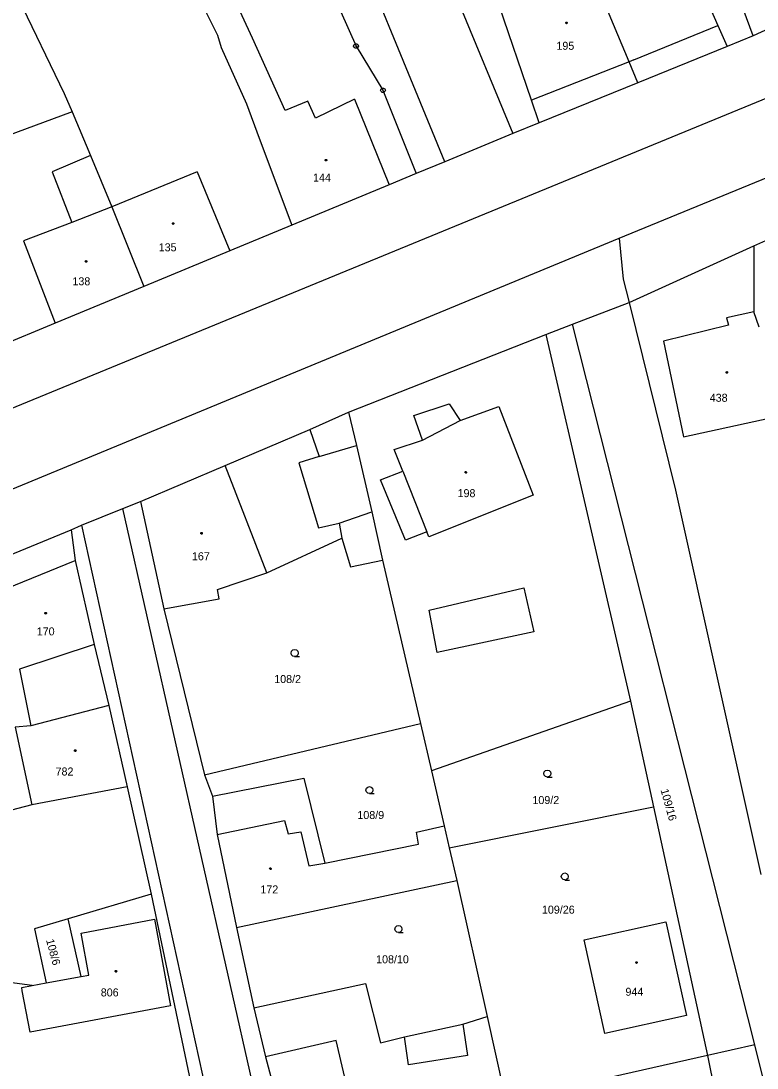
# Model space of a CAD drawing. Extents: x -757994 to -755874, y -1047691 to -1046119.
# Drawn here: x -756609.7 to -756531.6, y -1046918.4 to -1046807.2 of the extents above; entities that cross this region are included whole.
import ezdxf

# ---------------------------------------------------------------- set-up
doc = ezdxf.new("R2010")
doc.units = 0
doc.layers.add('katastrální mapa', color=7, linetype='Continuous')

msp = doc.modelspace()

# ---------------------------------------------------------------- linework, layer by layer
at = {"layer": 'katastrální mapa'}
for p, q in [((-756627.02, -1046769.47), (-756605.13, -1046814.89)), ((-756612.98, -1046849.23), (-756440.95, -1046778.5)), ((-756540.07, -1046797.73), (-756535.71, -1046807.66)), ((-756545.15, -1046811.51), (-756549.35, -1046801.44)), ((-756546.19, -1046830.24), (-756476.55, -1046801.65)), ((-756564.54, -1046802.11), (-756557.5, -1046819.13)), ((-756585.13, -1046808.98), (-756587.56, -1046803.75)), ((-756590.66, -1046805.08), (-756588.87, -1046808.69)), ((-756523.9, -1046805.07), (-756531.97, -1046808.74)), ((-756555.52, -1046815.57), (-756558.94, -1046805.54)), ((-756531.97, -1046808.74), (-756533.02, -1046805.87)), ((-756544.64, -1046811.31), (-756535.71, -1046807.66)), ((-756535.71, -1046807.66), (-756534.74, -1046809.87)), ((-756588.87, -1046808.69), (-756588.47, -1046810)), ((-756581.66, -1046816.68), (-756585.13, -1046808.98)), ((-756531.97, -1046808.74), (-756534.74, -1046809.87)), ((-756588.47, -1046810), (-756585.76, -1046815.97)), ((-756574.2, -1046809.83), (-756574.08, -1046809.83)), ((-756534.74, -1046809.87), (-756544.22, -1046813.73)), ((-756545.15, -1046811.51), (-756555.52, -1046815.57)), ((-756544.64, -1046811.31), (-756545.15, -1046811.51)), ((-756544.22, -1046813.73), (-756545.15, -1046811.51)), ((-756544.22, -1046813.73), (-756554.7, -1046817.99)), ((-756605.13, -1046814.89), (-756604.28, -1046816.83)), ((-756571.34, -1046814.53), (-756571.22, -1046814.53)), ((-756585.76, -1046815.97), (-756584.42, -1046819.61)), ((-756579.26, -1046815.68), (-756581.66, -1046816.68)), ((-756578.43, -1046817.51), (-756579.26, -1046815.68)), ((-756574.3, -1046815.48), (-756578.43, -1046817.51)), ((-756574.3, -1046815.48), (-756570.62, -1046824.57)), ((-756554.7, -1046817.99), (-756555.52, -1046815.57)), ((-756604.28, -1046816.83), (-756615.03, -1046820.81)), ((-756604.28, -1046816.83), (-756602.34, -1046821.46)), ((-756554.7, -1046817.99), (-756557.5, -1046819.13)), ((-756584.42, -1046819.61), (-756580.97, -1046828.86)), ((-756557.5, -1046819.13), (-756564.73, -1046822.13)), ((-756602.34, -1046821.46), (-756606.43, -1046823.18)), ((-756602.34, -1046821.46), (-756600.06, -1046826.91)), ((-756564.73, -1046822.13), (-756567.75, -1046823.38)), ((-756606.43, -1046823.18), (-756604.33, -1046828.56)), ((-756591.01, -1046823.2), (-756600.06, -1046826.91)), ((-756591.01, -1046823.2), (-756587.53, -1046831.58)), ((-756568.87, -1046823.84), (-756570.62, -1046824.57)), ((-756567.75, -1046823.38), (-756568.87, -1046823.84)), ((-756570.62, -1046824.57), (-756580.97, -1046828.86)), ((-756600.06, -1046826.91), (-756604.33, -1046828.56)), ((-756600.06, -1046826.91), (-756596.68, -1046835.37)), ((-756604.33, -1046828.56), (-756609.46, -1046830.53)), ((-756580.97, -1046828.86), (-756587.53, -1046831.58)), ((-756531.88, -1046831.06), (-756527.35, -1046829.01)), ((-756698.86, -1046893.31), (-756546.19, -1046830.24)), ((-756609.46, -1046830.53), (-756606.1, -1046839.27)), ((-756546.19, -1046830.24), (-756545.76, -1046834.59)), ((-756587.53, -1046831.58), (-756596.68, -1046835.37)), ((-756545.15, -1046837.07), (-756531.88, -1046831.06)), ((-756531.88, -1046831.06), (-756531.88, -1046838.07)), ((-756545.76, -1046834.59), (-756545.15, -1046837.07)), ((-756596.68, -1046835.37), (-756606.1, -1046839.27)), ((-756551.17, -1046839.38), (-756545.15, -1046837.07)), ((-756545.15, -1046837.07), (-756540.22, -1046857.01)), ((-756531.88, -1046838.07), (-756534.8, -1046838.69)), ((-756531.33, -1046839.67), (-756531.88, -1046838.07)), ((-756606.1, -1046839.27), (-756613.31, -1046842.26)), ((-756553.98, -1046840.46), (-756551.17, -1046839.38)), ((-756531.78, -1046915.9), (-756551.17, -1046839.38)), ((-756534.6, -1046839.46), (-756541.49, -1046841.19)), ((-756534.8, -1046838.69), (-756534.6, -1046839.46)), ((-756574.93, -1046848.73), (-756553.98, -1046840.46)), ((-756553.98, -1046840.46), (-756545, -1046879.4)), ((-756541.49, -1046841.19), (-756539.35, -1046851.35)), ((-756568.02, -1046849.08), (-756564.25, -1046847.83)), ((-756564.25, -1046847.83), (-756563.1, -1046849.6)), ((-756563.1, -1046849.6), (-756558.98, -1046848.12)), ((-756558.98, -1046848.12), (-756555.32, -1046857.52)), ((-756579.05, -1046850.56), (-756574.93, -1046848.73)), ((-756574.93, -1046848.73), (-756574.11, -1046852.27)), ((-756567.09, -1046851.7), (-756568.02, -1046849.08)), ((-756567.09, -1046851.7), (-756563.1, -1046849.6)), ((-756539.35, -1046851.35), (-756529.15, -1046849.09)), ((-756588.05, -1046854.37), (-756579.05, -1046850.56)), ((-756579.05, -1046850.56), (-756578.06, -1046853.43)), ((-756570.09, -1046852.68), (-756567.09, -1046851.7)), ((-756578.06, -1046853.43), (-756574.11, -1046852.27)), ((-756574.11, -1046852.27), (-756572.46, -1046859.3)), ((-756569.19, -1046854.97), (-756570.09, -1046852.68)), ((-756578.06, -1046853.43), (-756580.22, -1046854.09)), ((-756580.22, -1046854.09), (-756578.13, -1046860.99)), ((-756597.02, -1046858.19), (-756588.05, -1046854.37)), ((-756583.6, -1046865.78), (-756588.05, -1046854.37)), ((-756571.56, -1046855.91), (-756569.19, -1046854.97)), ((-756569.19, -1046854.97), (-756566.62, -1046861.43)), ((-756568.88, -1046862.29), (-756571.56, -1046855.91)), ((-756555.32, -1046857.52), (-756566.42, -1046861.96)), ((-756540.22, -1046857.01), (-756531.14, -1046897.8)), ((-756598.91, -1046858.96), (-756597.02, -1046858.19)), ((-756597.02, -1046858.19), (-756594.54, -1046869.59)), ((-756603.28, -1046860.72), (-756598.91, -1046858.96)), ((-756558.92, -1047036.01), (-756598.91, -1046858.96)), ((-756575.93, -1046860.49), (-756572.46, -1046859.3)), ((-756572.46, -1046859.3), (-756571.34, -1046864.42)), ((-756604.39, -1046861.2), (-756603.28, -1046860.72)), ((-756603.28, -1046860.72), (-756564.51, -1047036.98)), ((-756578.13, -1046860.99), (-756575.93, -1046860.49)), ((-756575.93, -1046860.49), (-756575.64, -1046862.11)), ((-756614.27, -1046865.28), (-756604.39, -1046861.2)), ((-756604.39, -1046861.2), (-756603.96, -1046864.46)), ((-756566.62, -1046861.43), (-756568.88, -1046862.29)), ((-756566.42, -1046861.96), (-756566.62, -1046861.43)), ((-756583.6, -1046865.78), (-756575.64, -1046862.11)), ((-756575.64, -1046862.11), (-756574.74, -1046865.13)), ((-756613.08, -1046868.17), (-756603.96, -1046864.46)), ((-756603.96, -1046864.46), (-756601.95, -1046873.39)), ((-756574.74, -1046865.13), (-756571.34, -1046864.42)), ((-756571.34, -1046864.42), (-756567.28, -1046881.77)), ((-756588.84, -1046867.54), (-756583.6, -1046865.78)), ((-756588.66, -1046868.55), (-756588.84, -1046867.54)), ((-756566.38, -1046869.73), (-756556.33, -1046867.36)), ((-756556.33, -1046867.36), (-756555.26, -1046872.03)), ((-756594.54, -1046869.59), (-756588.66, -1046868.55)), ((-756594.54, -1046869.59), (-756590.22, -1046887.21)), ((-756565.53, -1046874.23), (-756566.38, -1046869.73)), ((-756555.26, -1046872.03), (-756565.53, -1046874.23)), ((-756601.95, -1046873.39), (-756609.89, -1046875.99)), ((-756601.95, -1046873.39), (-756600.38, -1046879.88)), ((-756609.89, -1046875.99), (-756608.69, -1046882.01)), ((-756545, -1046879.4), (-756566.12, -1046886.81)), ((-756545, -1046879.4), (-756542.56, -1046890.64)), ((-756600.38, -1046879.88), (-756608.69, -1046882.01)), ((-756600.38, -1046879.88), (-756598.43, -1046888.49)), ((-756608.69, -1046882.01), (-756610.34, -1046882.18)), ((-756590.22, -1046887.21), (-756567.28, -1046881.77)), ((-756567.28, -1046881.77), (-756566.12, -1046886.81)), ((-756610.34, -1046882.18), (-756608.57, -1046890.43)), ((-756590.22, -1046887.21), (-756589.4, -1046889.5)), ((-756589.4, -1046889.5), (-756579.7, -1046887.58)), ((-756579.7, -1046887.58), (-756577.46, -1046896.61)), ((-756566.12, -1046886.81), (-756564.79, -1046892.63)), ((-756598.43, -1046888.49), (-756608.57, -1046890.43)), ((-756598.43, -1046888.49), (-756595.9, -1046899.9)), ((-756589.4, -1046889.5), (-756588.88, -1046893.57)), ((-756608.57, -1046890.43), (-756615.16, -1046892.14)), ((-756564.24, -1046894.99), (-756542.56, -1046890.64)), ((-756542.56, -1046890.64), (-756536.82, -1046917.03)), ((-756588.88, -1046893.57), (-756581.75, -1046892.06)), ((-756581.75, -1046892.06), (-756581.35, -1046893.48)), ((-756567.72, -1046893.32), (-756564.79, -1046892.63)), ((-756564.79, -1046892.63), (-756564.24, -1046894.99)), ((-756588.88, -1046893.57), (-756586.85, -1046903.44)), ((-756581.35, -1046893.48), (-756580.01, -1046893.28)), ((-756580.01, -1046893.28), (-756579.15, -1046896.9)), ((-756567.52, -1046894.58), (-756567.72, -1046893.32)), ((-756577.46, -1046896.61), (-756567.52, -1046894.58)), ((-756564.24, -1046894.99), (-756563.43, -1046898.44)), ((-756579.15, -1046896.9), (-756577.46, -1046896.61)), ((-756586.85, -1046903.44), (-756563.43, -1046898.44)), ((-756563.43, -1046898.44), (-756560.2, -1046912.9)), ((-756595.9, -1046899.9), (-756604.72, -1046902.52)), ((-756595.9, -1046899.9), (-756591.53, -1046920.69)), ((-756604.72, -1046902.52), (-756608.3, -1046903.59)), ((-756603.34, -1046908.65), (-756604.72, -1046902.52)), ((-756603.34, -1046904.04), (-756595.55, -1046902.54)), ((-756595.55, -1046902.54), (-756593.85, -1046911.75)), ((-756608.3, -1046903.59), (-756607.04, -1046909.33)), ((-756602.51, -1046908.5), (-756603.34, -1046904.04)), ((-756586.85, -1046903.44), (-756584.98, -1046911.96)), ((-756607.04, -1046909.33), (-756603.34, -1046908.65)), ((-756603.34, -1046908.65), (-756602.51, -1046908.5)), ((-756608.54, -1046909.61), (-756610.94, -1046909.27)), ((-756609.65, -1046909.82), (-756608.54, -1046909.61)), ((-756609.59, -1046910.15), (-756609.65, -1046909.82)), ((-756608.54, -1046909.61), (-756607.04, -1046909.33)), ((-756584.98, -1046911.96), (-756573.12, -1046909.38)), ((-756573.12, -1046909.38), (-756571.55, -1046915.68)), ((-756608.76, -1046914.54), (-756609.59, -1046910.15)), ((-756593.85, -1046911.75), (-756608.76, -1046914.54)), ((-756584.98, -1046911.96), (-756583.74, -1046917.16)), ((-756562.81, -1046913.7), (-756560.2, -1046912.9)), ((-756560.2, -1046912.9), (-756558.23, -1046921.84)), ((-756568.99, -1046915.04), (-756562.81, -1046913.7)), ((-756562.81, -1046913.7), (-756562.29, -1046917.02)), ((-756571.55, -1046915.68), (-756568.99, -1046915.04)), ((-756568.57, -1046918.03), (-756568.99, -1046915.04)), ((-756576.26, -1046915.43), (-756583.74, -1046917.16)), ((-756573.98, -1046925.11), (-756576.26, -1046915.43)), ((-756531.78, -1046915.9), (-756536.82, -1046917.03)), ((-756524.1, -1046947.17), (-756531.78, -1046915.9)), ((-756583.74, -1046917.16), (-756581.2, -1046926.8)), ((-756562.29, -1046917.02), (-756568.57, -1046918.03)), ((-756536.82, -1046917.03), (-756558.23, -1046921.84)), ((-756536.82, -1046917.03), (-756535.4, -1046924.06))]:
    msp.add_line(p, q, dxfattribs=at)
for points in [[(-756564.73, -1046822.13), (-756576.84, -1046792.58), (-756572.51, -1046790.92), (-756584.28, -1046767.68), (-756605.17, -1046780.74)], [(-756581.05, -1046794.27), (-756574.14, -1046809.83), (-756571.28, -1046814.53), (-756567.75, -1046823.38)], [(-756580.65, -1046874.66), (-756580.84, -1046874.61), (-756580.98, -1046874.48), (-756581.03, -1046874.29), (-756580.98, -1046874.11), (-756580.84, -1046873.97), (-756580.66, -1046873.92), (-756580.47, -1046873.97), (-756580.34, -1046874.11), (-756580.29, -1046874.3), (-756580.34, -1046874.49), (-756580.47, -1046874.62), (-756580.66, -1046874.67), (-756580.16, -1046874.67)], [(-756553.82, -1046887.46), (-756554.01, -1046887.41), (-756554.15, -1046887.27), (-756554.2, -1046887.09), (-756554.15, -1046886.91), (-756554.01, -1046886.77), (-756553.83, -1046886.72), (-756553.64, -1046886.77), (-756553.5, -1046886.91), (-756553.46, -1046887.1), (-756553.5, -1046887.28), (-756553.64, -1046887.42), (-756553.83, -1046887.47), (-756553.33, -1046887.47)], [(-756572.71, -1046889.21), (-756572.9, -1046889.16), (-756573.03, -1046889.02), (-756573.09, -1046888.84), (-756573.03, -1046888.66), (-756572.9, -1046888.52), (-756572.72, -1046888.47), (-756572.53, -1046888.52), (-756572.4, -1046888.66), (-756572.35, -1046888.85), (-756572.4, -1046889.03), (-756572.53, -1046889.17), (-756572.72, -1046889.22), (-756572.22, -1046889.22)], [(-756551.97, -1046898.39), (-756552.16, -1046898.34), (-756552.29, -1046898.21), (-756552.35, -1046898.02), (-756552.29, -1046897.84), (-756552.16, -1046897.7), (-756551.98, -1046897.65), (-756551.79, -1046897.7), (-756551.66, -1046897.84), (-756551.6, -1046898.03), (-756551.66, -1046898.22), (-756551.79, -1046898.35), (-756551.98, -1046898.4), (-756551.48, -1046898.4)], [(-756569.63, -1046903.97), (-756569.82, -1046903.92), (-756569.96, -1046903.78), (-756570.01, -1046903.6), (-756569.96, -1046903.42), (-756569.82, -1046903.28), (-756569.64, -1046903.23), (-756569.45, -1046903.28), (-756569.32, -1046903.42), (-756569.27, -1046903.61), (-756569.32, -1046903.79), (-756569.45, -1046903.93), (-756569.64, -1046903.98), (-756569.14, -1046903.98)]]:
    msp.add_lwpolyline(points, dxfattribs=at)
for points in [[(-756551.79, -1046807.28), (-756551.74, -1046807.29), (-756551.72, -1046807.34), (-756551.71, -1046807.37), (-756551.72, -1046807.42), (-756551.76, -1046807.45), (-756551.79, -1046807.46), (-756551.84, -1046807.44), (-756551.86, -1046807.41), (-756551.88, -1046807.37), (-756551.86, -1046807.33), (-756551.83, -1046807.29)], [(-756574.07, -1046809.59), (-756573.94, -1046809.68), (-756573.89, -1046809.83), (-756573.94, -1046809.97), (-756574.07, -1046810.06), (-756574.22, -1046810.06), (-756574.35, -1046809.97), (-756574.4, -1046809.83), (-756574.35, -1046809.68), (-756574.22, -1046809.59)], [(-756571.21, -1046814.29), (-756571.08, -1046814.38), (-756571.03, -1046814.53), (-756571.08, -1046814.67), (-756571.21, -1046814.76), (-756571.36, -1046814.76), (-756571.49, -1046814.67), (-756571.54, -1046814.53), (-756571.49, -1046814.38), (-756571.36, -1046814.29)], [(-756577.34, -1046821.88), (-756577.29, -1046821.89), (-756577.26, -1046821.93), (-756577.25, -1046821.96), (-756577.26, -1046822), (-756577.3, -1046822.04), (-756577.34, -1046822.04), (-756577.39, -1046822.03), (-756577.42, -1046822), (-756577.43, -1046821.96), (-756577.42, -1046821.92), (-756577.38, -1046821.88)], [(-756593.56, -1046828.6), (-756593.51, -1046828.61), (-756593.49, -1046828.65), (-756593.48, -1046828.68), (-756593.49, -1046828.73), (-756593.53, -1046828.76), (-756593.56, -1046828.77), (-756593.6, -1046828.75), (-756593.64, -1046828.72), (-756593.65, -1046828.68), (-756593.64, -1046828.64), (-756593.6, -1046828.6)], [(-756602.81, -1046832.62), (-756602.76, -1046832.62), (-756602.74, -1046832.67), (-756602.73, -1046832.7), (-756602.74, -1046832.74), (-756602.78, -1046832.78), (-756602.81, -1046832.78), (-756602.85, -1046832.77), (-756602.89, -1046832.74), (-756602.9, -1046832.7), (-756602.89, -1046832.66), (-756602.85, -1046832.62)], [(-756534.76, -1046844.41), (-756534.71, -1046844.42), (-756534.69, -1046844.46), (-756534.68, -1046844.49), (-756534.69, -1046844.53), (-756534.73, -1046844.57), (-756534.76, -1046844.58), (-756534.8, -1046844.56), (-756534.84, -1046844.53), (-756534.85, -1046844.49), (-756534.84, -1046844.45), (-756534.79, -1046844.41)], [(-756562.48, -1046855.01), (-756562.43, -1046855.02), (-756562.41, -1046855.07), (-756562.4, -1046855.1), (-756562.41, -1046855.15), (-756562.45, -1046855.18), (-756562.48, -1046855.19), (-756562.52, -1046855.17), (-756562.55, -1046855.14), (-756562.57, -1046855.1), (-756562.55, -1046855.05), (-756562.51, -1046855.02)], [(-756590.55, -1046861.49), (-756590.5, -1046861.5), (-756590.48, -1046861.55), (-756590.47, -1046861.58), (-756590.48, -1046861.62), (-756590.52, -1046861.66), (-756590.55, -1046861.67), (-756590.6, -1046861.65), (-756590.62, -1046861.62), (-756590.64, -1046861.58), (-756590.62, -1046861.53), (-756590.59, -1046861.5)], [(-756607.1, -1046869.98), (-756607.05, -1046869.99), (-756607.02, -1046870.03), (-756607.01, -1046870.06), (-756607.02, -1046870.11), (-756607.07, -1046870.14), (-756607.1, -1046870.15), (-756607.15, -1046870.13), (-756607.18, -1046870.1), (-756607.19, -1046870.06), (-756607.18, -1046870.02), (-756607.14, -1046869.98)], [(-756603.96, -1046884.58), (-756603.91, -1046884.59), (-756603.89, -1046884.63), (-756603.88, -1046884.66), (-756603.89, -1046884.71), (-756603.93, -1046884.74), (-756603.96, -1046884.75), (-756604, -1046884.73), (-756604.03, -1046884.7), (-756604.04, -1046884.66), (-756604.03, -1046884.62), (-756603.99, -1046884.58)], [(-756583.23, -1046897.11), (-756583.18, -1046897.12), (-756583.16, -1046897.16), (-756583.15, -1046897.19), (-756583.16, -1046897.23), (-756583.2, -1046897.27), (-756583.23, -1046897.27), (-756583.27, -1046897.26), (-756583.3, -1046897.23), (-756583.32, -1046897.19), (-756583.3, -1046897.15), (-756583.26, -1046897.11)], [(-756549.92, -1046904.74), (-756541.24, -1046902.84), (-756539.05, -1046912.8), (-756547.73, -1046914.7)], [(-756544.36, -1046907.08), (-756544.31, -1046907.09), (-756544.28, -1046907.13), (-756544.27, -1046907.16), (-756544.28, -1046907.21), (-756544.33, -1046907.24), (-756544.36, -1046907.25), (-756544.41, -1046907.23), (-756544.44, -1046907.2), (-756544.45, -1046907.16), (-756544.44, -1046907.12), (-756544.4, -1046907.08)], [(-756599.64, -1046908), (-756599.59, -1046908.01), (-756599.57, -1046908.06), (-756599.55, -1046908.09), (-756599.57, -1046908.14), (-756599.6, -1046908.17), (-756599.64, -1046908.18), (-756599.69, -1046908.16), (-756599.72, -1046908.13), (-756599.73, -1046908.09), (-756599.72, -1046908.04), (-756599.68, -1046908.01)]]:
    msp.add_lwpolyline(points, close=True, dxfattribs=at)

# ---------------------------------------------------------------- texts
for s, p in [('195', (-756552.86, -1046810.23)), ('144', (-756578.71, -1046824.23)), ('135', (-756595.1, -1046831.63)), ('138', (-756604.26, -1046835.24)), ('438', (-756536.58, -1046847.61)), ('198', (-756563.36, -1046857.74)), ('167', (-756591.57, -1046864.44)), ('170', (-756608.05, -1046872.42)), ('108/2', (-756582.83, -1046877.48)), ('782', (-756606.05, -1046887.3)), ('109/2', (-756555.41, -1046890.33)), ('108/9', (-756574, -1046891.92)), ('172', (-756584.3, -1046899.82)), ('109/26', (-756554.4, -1046901.97)), ('108/10', (-756572.01, -1046907.24)), ('944', (-756545.53, -1046910.69)), ('806', (-756601.25, -1046910.76))]:
    msp.add_text(s, height=0.85, dxfattribs=at).set_placement(p)
for s, rotation, p in [('109/16', 285.5622, (-756541.81, -1046888.84)), ('108/6', 285.1038, (-756607.07, -1046904.78))]:
    msp.add_text(s, height=0.85, rotation=rotation, dxfattribs=at).set_placement(p)

doc.saveas('drawing.dxf')
